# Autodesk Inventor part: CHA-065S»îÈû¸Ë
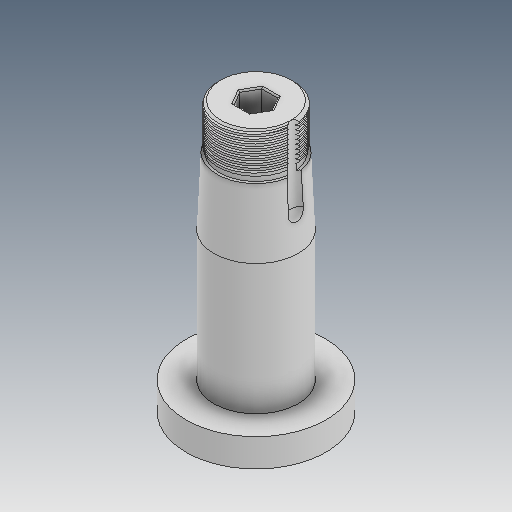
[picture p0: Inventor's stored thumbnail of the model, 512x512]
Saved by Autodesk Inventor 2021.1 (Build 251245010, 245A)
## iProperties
Created: 2019-12
Part Number: CHA-065S»îÈû¸Ë
Material: Ogólny
Document SubType Name: Modeling
Designer: user
Density: 1 g/cm^3
Appearance: Domyślna
Author: user
Revision Number: ÈÎºÎ
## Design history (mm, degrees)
feature "ÊäÈë1"
node "Bryła1"
